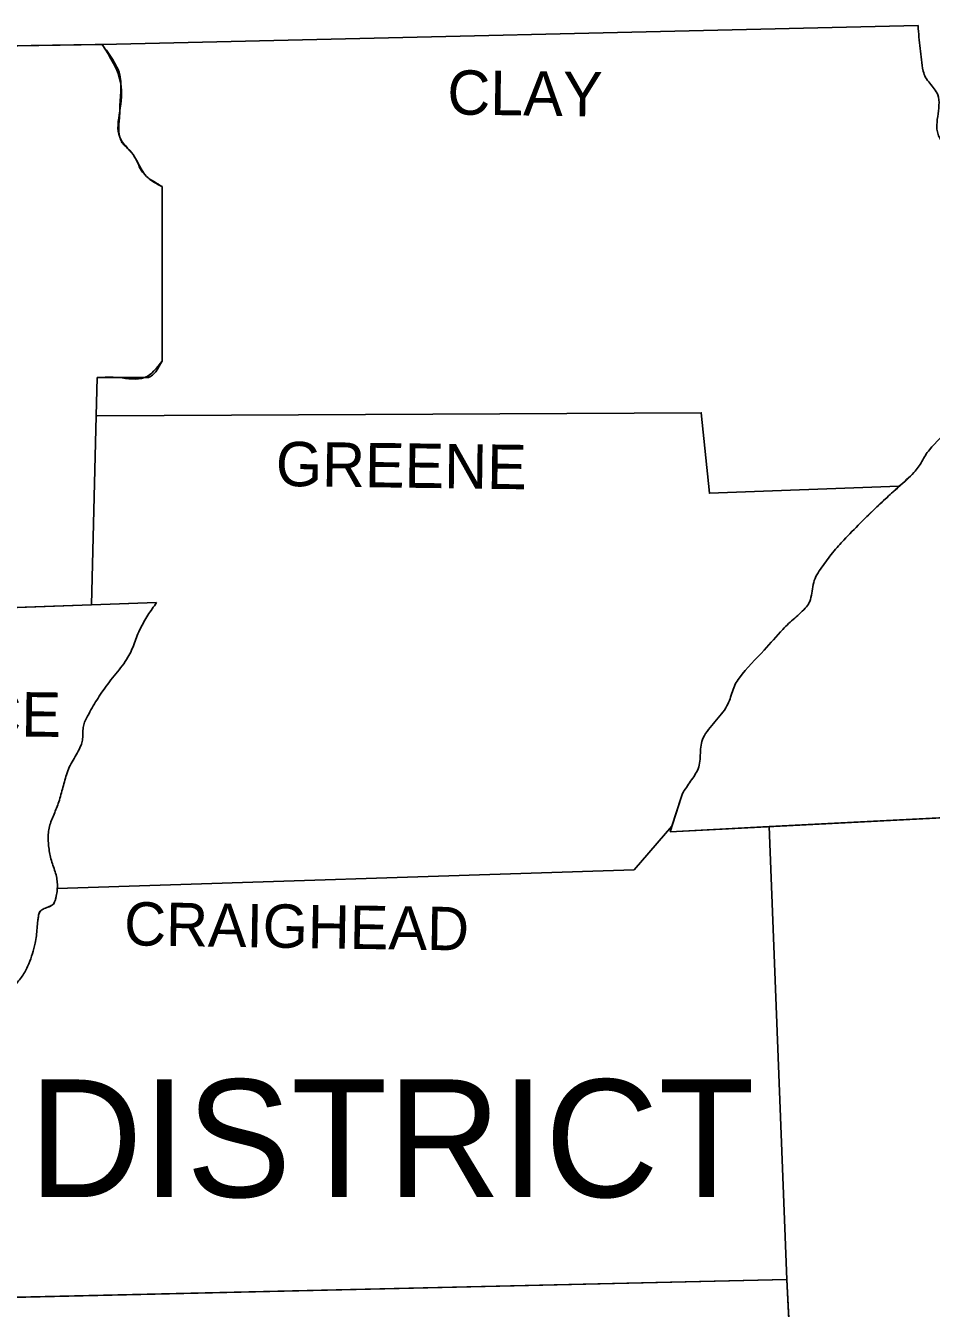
# Model space of a CAD drawing. Extents: x 1368042 to 1371376, y 380392 to 382637.
# Drawn here: x 1370078.3 to 1370261.4, y 381501.2 to 381760.7 of the extents above; entities that cross this region are included whole.
import ezdxf

# ---------------------------------------------------------------- set-up
doc = ezdxf.new("R2010")
doc.units = 0
doc.layers.add('Default', color=7, linetype='Continuous')
doc.layers.add('R_No Plot', color=7, linetype='Continuous')

msp = doc.modelspace()

# ---------------------------------------------------------------- linework, layer by layer
at = {"layer": 'Default'}
for p, q in [((1370092.56, 381681.8), (1370092.75, 381689.52)), ((1370208.64, 381597.64), (1370210.89, 381604.58))]:
    msp.add_line(p, q, dxfattribs=at)
for points in [[(1369113.15, 381751.13), (1369450.82, 381750.92), (1369747.14, 381751.54), (1370096.71, 381756.97), (1370258.76, 381760.73)], [(1370105.9, 381728.16), (1370105.9, 381692.87)], [(1370091.65, 381643.52), (1370092.56, 381681.8), (1370092.75, 381681.8), (1370214.91, 381682.42), (1370216.58, 381666.14), (1370254.9, 381667.53)], [(1370027.8, 381641.29), (1370104.79, 381643.99)], [(1370208.64, 381597.64), (1370367.14, 381605.79)], [(1370084.72, 381586.14), (1370201.33, 381589.92), (1370209, 381598.75)], [(1370228.64, 381598.67), (1370232.24, 381507.02), (1370236.49, 381421.47)], [(1370232.24, 381507.02), (1370038.09, 381502.59)]]:
    msp.add_lwpolyline(points, dxfattribs=at)
for points in [[(1370258.76, 381760.73), (1370258.94, 381758.43), (1370259.18, 381756.13), (1370259.47, 381753.83), (1370259.81, 381751.54), (1370260.29, 381750.25), (1370261.14, 381749.08), (1370262.05, 381747.94), (1370262.73, 381746.74), (1370262.99, 381744.62), (1370262.73, 381742.34), (1370262.57, 381740.06), (1370262.73, 381738.98), (1370263.15, 381737.97), (1370264.73, 381735.92), (1370266.7, 381734.21), (1370268.19, 381733.22), (1370269.73, 381732.34), (1370271.27, 381731.46), (1370272.75, 381730.45), (1370275.76, 381727.78), (1370277.05, 381726.22), (1370277.64, 381725.35), (1370278.18, 381724.4), (1370278.94, 381722.63), (1370279.38, 381720.85), (1370279.53, 381719.07), (1370279.43, 381717.3), (1370279.07, 381715.47), (1370278.56, 381713.66), (1370278.06, 381711.83), (1370277.76, 381709.99), (1370277.65, 381707.96), (1370277.58, 381705.92), (1370277.49, 381703.88), (1370277.35, 381701.84), (1370276.51, 381694.75), (1370276.12, 381691.48), (1370275.79, 381689.86), (1370275.56, 381689.06), (1370275.26, 381688.27), (1370273.08, 381685.38), (1370270.25, 381683.05), (1370269.05, 381682.1), (1370267.83, 381681.18), (1370266.62, 381680.26), (1370265.44, 381679.29), (1370261.06, 381674.91), (1370260.24, 381673.78), (1370259.53, 381672.57), (1370258.81, 381671.38), (1370257.93, 381670.31), (1370252.5, 381665.3), (1370247.07, 381660.08), (1370242.68, 381655.49), (1370241.48, 381654.1), (1370240.37, 381652.65), (1370239.31, 381651.16), (1370238.3, 381649.64), (1370237.66, 381648.07), (1370237.35, 381646.34), (1370236.99, 381644.64), (1370236.68, 381643.86), (1370236.21, 381643.17), (1370235.05, 381641.97), (1370233.82, 381640.86), (1370232.58, 381639.75), (1370231.41, 381638.57), (1370227.65, 381634.4), (1370222.63, 381628.76), (1370221.81, 381627.47), (1370221.24, 381626.02), (1370220.74, 381624.53), (1370220.13, 381623.12), (1370219.01, 381621.47), (1370217.7, 381619.91), (1370216.4, 381618.34), (1370215.33, 381616.65), (1370214.88, 381615.15), (1370214.75, 381613.53), (1370214.65, 381611.9), (1370214.28, 381610.38), (1370213.6, 381609.09), (1370212.77, 381607.85), (1370211.92, 381606.62), (1370211.15, 381605.37), (1370210.89, 381604.58)], [(1370093.76, 381756.93), (1370097.55, 381749.04), (1370097.34, 381743.4), (1370097.34, 381738.18), (1370100.05, 381734.63), (1370102.77, 381730.24), (1370105.9, 381728.16)], [(1370105.9, 381692.87), (1370102.35, 381689.52), (1370097.13, 381689.52), (1370092.75, 381689.52)], [(1370104.79, 381643.99), (1370103.03, 381641.45), (1370101.52, 381638.78), (1370100.87, 381637.33), (1370100.31, 381635.83), (1370099.73, 381634.35), (1370099.01, 381632.93), (1370097.84, 381631.21), (1370096.55, 381629.57), (1370095.24, 381627.94), (1370094, 381626.25), (1370091.98, 381623.09), (1370091.07, 381621.46), (1370090.24, 381619.78), (1370089.96, 381618.72), (1370089.89, 381617.59), (1370089.84, 381616.47), (1370089.61, 381615.39), (1370088.93, 381613.92), (1370088.12, 381612.49), (1370087.32, 381611.05), (1370086.69, 381609.55), (1370086.25, 381608.09), (1370085.85, 381606.62), (1370085.45, 381605.15), (1370085.02, 381603.7), (1370084.57, 381602.44), (1370084.06, 381601.2), (1370083.56, 381599.96), (1370083.14, 381598.69), (1370082.91, 381597.41), (1370082.87, 381596.09), (1370082.97, 381594.76), (1370083.14, 381593.47), (1370083.43, 381592.15), (1370083.84, 381590.85), (1370084.28, 381589.55), (1370084.6, 381588.25), (1370084.73, 381587.06), (1370084.7, 381585.85), (1370084.52, 381584.63), (1370084.37, 381584.03), (1370084.18, 381583.44), (1370083.56, 381582.73), (1370082.58, 381582.29), (1370081.62, 381581.86), (1370081.05, 381581.15), (1370080.89, 381580.41), (1370080.77, 381579.65), (1370080.63, 381578.12), (1370080.49, 381576.59), (1370080.22, 381575.09), (1370079.67, 381572.99), (1370078.96, 381570.92), (1370077.8, 381568.7), (1370077.08, 381567.69), (1370076.25, 381566.74), (1370075.3, 381565.89), (1370074.27, 381565.14), (1370073.24, 381564.41), (1370072.28, 381563.61), (1370071.21, 381562.45), (1370070.21, 381561.21), (1370069.21, 381559.98), (1370068.1, 381558.8), (1370066.64, 381557.65), (1370065.84, 381557.16), (1370064.97, 381556.72)]]:
    msp.add_spline(points, degree=3, dxfattribs=at)
at = {"layer": 'R_No Plot'}
for p, q in [((1370093.76, 381756.93), (1369939.22, 381754.53)), ((1370105.9, 381692.87), (1370105.9, 381728.16)), ((1370105.9, 381728.16), (1370105.9, 381692.87)), ((1370092.56, 381681.8), (1370092.75, 381689.52)), ((1370092.75, 381689.52), (1370092.56, 381681.8)), ((1370091.65, 381643.52), (1370092.56, 381681.8)), ((1370027.8, 381641.29), (1370091.65, 381643.52)), ((1370091.65, 381643.52), (1370027.8, 381641.29)), ((1370104.79, 381643.99), (1370091.65, 381643.52)), ((1370091.65, 381643.52), (1370104.79, 381643.99)), ((1370209, 381598.75), (1370210.89, 381604.58)), ((1370208.64, 381597.64), (1370209, 381598.75)), ((1370228.64, 381598.67), (1370208.64, 381597.64)), ((1370232.24, 381507.02), (1370228.64, 381598.67)), ((1370038.09, 381502.59), (1370232.24, 381507.02)), ((1370232.24, 381507.02), (1370038.09, 381502.59)), ((1370236.49, 381421.47), (1370232.24, 381507.02))]:
    msp.add_line(p, q, dxfattribs=at)
for points in [[(1370258.76, 381760.73), (1370096.71, 381756.97), (1370093.76, 381756.93)], [(1370254.9, 381667.53), (1370216.58, 381666.14), (1370214.91, 381682.42), (1370092.75, 381681.8), (1370092.56, 381681.8), (1370091.65, 381643.52)], [(1370092.56, 381681.8), (1370092.75, 381681.8), (1370214.91, 381682.42), (1370216.58, 381666.14), (1370254.9, 381667.53)], [(1370254.9, 381667.53), (1370254.9, 381667.53)], [(1370254.9, 381667.53), (1370254.9, 381667.53)], [(1370367.14, 381605.79), (1370365.81, 381605.72), (1370228.64, 381598.67)], [(1370084.72, 381586.14), (1370201.33, 381589.92), (1370209, 381598.75)], [(1370209, 381598.75), (1370201.33, 381589.92), (1370084.72, 381586.14)], [(1370228.64, 381598.67), (1370232.24, 381507.02), (1370236.49, 381421.47)]]:
    msp.add_lwpolyline(points, dxfattribs=at)
for points in [[(1370277.59, 381706.18), (1370277.65, 381707.96), (1370277.76, 381709.99), (1370278.06, 381711.83), (1370278.56, 381713.66), (1370279.07, 381715.47), (1370279.43, 381717.3), (1370279.53, 381719.07), (1370279.38, 381720.85), (1370278.94, 381722.63), (1370278.18, 381724.4), (1370277.64, 381725.35), (1370277.05, 381726.22), (1370275.76, 381727.78), (1370272.75, 381730.45), (1370271.27, 381731.46), (1370269.73, 381732.34), (1370268.19, 381733.22), (1370266.7, 381734.21), (1370264.73, 381735.92), (1370263.15, 381737.97), (1370262.73, 381738.98), (1370262.57, 381740.06), (1370262.73, 381742.34), (1370262.99, 381744.62), (1370262.73, 381746.74), (1370262.05, 381747.94), (1370261.14, 381749.08), (1370260.29, 381750.25), (1370259.81, 381751.54), (1370259.47, 381753.83), (1370259.18, 381756.13), (1370258.94, 381758.43), (1370258.76, 381760.73)], [(1370105.9, 381728.16), (1370102.77, 381730.24), (1370100.05, 381734.63), (1370097.34, 381738.18), (1370097.34, 381743.4), (1370097.55, 381749.04), (1370093.76, 381756.93)], [(1370093.76, 381756.93), (1370094.35, 381756.14), (1370094.93, 381755.35), (1370095.48, 381754.54), (1370095.99, 381753.72)], [(1370097.34, 381738.18), (1370097.72, 381737.24), (1370098.37, 381736.44), (1370099.13, 381735.69), (1370099.5, 381735.31), (1370099.84, 381734.92)], [(1370104.69, 381728.92), (1370105.3, 381728.55), (1370105.9, 381728.16)], [(1370254.9, 381667.53), (1370257.93, 381670.31), (1370258.81, 381671.38), (1370259.53, 381672.57), (1370260.24, 381673.78), (1370261.06, 381674.91), (1370265.44, 381679.29), (1370266.62, 381680.26), (1370267.83, 381681.18), (1370269.05, 381682.1), (1370270.25, 381683.05), (1370273.08, 381685.38), (1370275.26, 381688.27), (1370275.56, 381689.06), (1370275.79, 381689.86), (1370276.12, 381691.48), (1370276.51, 381694.75), (1370277.35, 381701.84), (1370277.49, 381703.88), (1370277.58, 381705.92), (1370277.59, 381706.18)], [(1370092.75, 381689.52), (1370097.13, 381689.52), (1370102.35, 381689.52), (1370105.9, 381692.87)], [(1370243.75, 381656.64), (1370247.07, 381660.08), (1370249.77, 381662.7), (1370252.5, 381665.3), (1370254.9, 381667.53)], [(1370210.89, 381604.58), (1370211.15, 381605.37), (1370211.92, 381606.62), (1370212.77, 381607.85), (1370213.6, 381609.09), (1370214.28, 381610.38), (1370214.65, 381611.9), (1370214.75, 381613.53), (1370214.88, 381615.15), (1370215.33, 381616.65), (1370216.4, 381618.34), (1370217.7, 381619.91), (1370219.01, 381621.47), (1370220.13, 381623.12), (1370220.74, 381624.53), (1370221.24, 381626.02), (1370221.81, 381627.47), (1370222.63, 381628.76), (1370227.65, 381634.4), (1370231.41, 381638.57), (1370232.58, 381639.75), (1370233.82, 381640.86), (1370235.05, 381641.97), (1370236.21, 381643.17), (1370236.68, 381643.86), (1370236.99, 381644.64), (1370237.35, 381646.34), (1370237.66, 381648.07), (1370238.3, 381649.64), (1370239.31, 381651.16), (1370240.37, 381652.65), (1370241.48, 381654.1), (1370242.68, 381655.49), (1370243.75, 381656.64)], [(1370089.28, 381614.6), (1370089.61, 381615.39), (1370089.84, 381616.47), (1370089.89, 381617.59), (1370089.96, 381618.72), (1370090.24, 381619.78), (1370091.07, 381621.46), (1370091.98, 381623.09), (1370094, 381626.25), (1370095.24, 381627.94), (1370096.55, 381629.57), (1370097.84, 381631.21), (1370099.01, 381632.93), (1370099.73, 381634.35), (1370100.31, 381635.83), (1370100.87, 381637.33), (1370101.52, 381638.78), (1370103.03, 381641.45), (1370104.79, 381643.99)], [(1370104.79, 381643.99), (1370103.03, 381641.45), (1370101.52, 381638.78), (1370100.87, 381637.33), (1370100.31, 381635.83), (1370099.73, 381634.35), (1370099.01, 381632.93), (1370097.84, 381631.21), (1370096.55, 381629.57), (1370095.24, 381627.94), (1370094, 381626.25), (1370091.98, 381623.09), (1370091.07, 381621.46), (1370090.24, 381619.78), (1370089.96, 381618.72), (1370089.89, 381617.59), (1370089.84, 381616.47), (1370089.61, 381615.39), (1370089.28, 381614.6)], [(1370083.51, 381582.71), (1370083.56, 381582.73), (1370084.18, 381583.44), (1370084.37, 381584.03), (1370084.52, 381584.63), (1370084.7, 381585.85), (1370084.73, 381587.06), (1370084.6, 381588.25), (1370084.28, 381589.55), (1370083.84, 381590.85), (1370083.43, 381592.15), (1370083.14, 381593.47), (1370082.97, 381594.76), (1370082.87, 381596.09), (1370082.91, 381597.41), (1370083.14, 381598.69), (1370083.56, 381599.96), (1370084.06, 381601.2), (1370084.57, 381602.44), (1370085.02, 381603.7), (1370085.45, 381605.15), (1370085.85, 381606.62), (1370086.25, 381608.09), (1370086.69, 381609.55), (1370087.32, 381611.05), (1370088.12, 381612.49), (1370088.93, 381613.92), (1370089.28, 381614.6)], [(1370089.28, 381614.6), (1370088.93, 381613.92), (1370088.12, 381612.49), (1370087.32, 381611.05), (1370086.69, 381609.55), (1370086.25, 381608.09), (1370085.85, 381606.62), (1370085.45, 381605.15), (1370085.02, 381603.7), (1370084.57, 381602.44), (1370084.06, 381601.2), (1370083.56, 381599.96), (1370083.14, 381598.69), (1370082.91, 381597.41), (1370082.87, 381596.09), (1370082.97, 381594.76), (1370083.14, 381593.47), (1370083.43, 381592.15), (1370083.84, 381590.85), (1370084.28, 381589.55), (1370084.6, 381588.25), (1370084.73, 381587.06), (1370084.72, 381586.14)], [(1370084.72, 381586.14), (1370084.7, 381585.85), (1370084.52, 381584.63), (1370084.37, 381584.03), (1370084.18, 381583.44), (1370083.56, 381582.73), (1370083.51, 381582.71)], [(1370064.97, 381556.72), (1370065.84, 381557.16), (1370066.64, 381557.65), (1370068.1, 381558.8), (1370069.21, 381559.98), (1370070.21, 381561.21), (1370071.21, 381562.45), (1370072.28, 381563.61), (1370073.24, 381564.41), (1370074.27, 381565.14), (1370075.3, 381565.89), (1370076.25, 381566.74), (1370077.08, 381567.69), (1370077.8, 381568.7), (1370078.96, 381570.92), (1370079.67, 381572.99), (1370080.22, 381575.09), (1370080.49, 381576.59), (1370080.63, 381578.12), (1370080.77, 381579.65), (1370080.89, 381580.41), (1370081.05, 381581.15), (1370081.62, 381581.86), (1370082.58, 381582.29), (1370083.51, 381582.71)], [(1370083.51, 381582.71), (1370082.58, 381582.29), (1370081.62, 381581.86), (1370081.05, 381581.15), (1370080.89, 381580.41), (1370080.77, 381579.65), (1370080.63, 381578.12), (1370080.49, 381576.59), (1370080.22, 381575.09), (1370079.67, 381572.99), (1370078.96, 381570.92), (1370077.8, 381568.7), (1370077.08, 381567.69), (1370076.25, 381566.74), (1370075.3, 381565.89), (1370074.27, 381565.14), (1370073.24, 381564.41), (1370072.28, 381563.61), (1370071.21, 381562.45), (1370070.21, 381561.21), (1370069.21, 381559.98), (1370068.1, 381558.8), (1370066.64, 381557.65), (1370065.84, 381557.16), (1370064.97, 381556.72)]]:
    msp.add_spline(points, degree=3, dxfattribs=at)
for points in [[(1370095.99, 381753.72), (1370096.87, 381752.25), (1370097.51, 381750.7), (1370097.55, 381749.04), (1370097.6, 381747.16), (1370097.38, 381745.28), (1370097.34, 381743.4), (1370097.3, 381741.66), (1370097.01, 381739.92), (1370097.34, 381738.18)], [(1370099.84, 381734.92), (1370099.92, 381734.82), (1370099.99, 381734.73), (1370100.05, 381734.63), (1370100.99, 381733.24), (1370101.47, 381731.47), (1370102.72, 381730.29)], [(1370102.72, 381730.29), (1370102.73, 381730.28), (1370102.75, 381730.26), (1370102.77, 381730.24), (1370103.35, 381729.71), (1370104.02, 381729.31), (1370104.69, 381728.92)], [(1370105.9, 381692.87), (1370105.09, 381691.4), (1370103.98, 381689.52), (1370102.35, 381689.52), (1370100.61, 381689.52), (1370098.87, 381689.52), (1370097.13, 381689.52), (1370095.67, 381689.52), (1370094.21, 381689.52), (1370092.75, 381689.52)]]:
    msp.add_open_spline(points, degree=3, dxfattribs=at)

# ---------------------------------------------------------------- texts
at = {"layer": 'Default'}
for s, height, rotation, p in [('CLAY', 8.978, 359.2258, (1370163.54, 381742.77)), ('GREENE', 8.981, 359.2361, (1370128.87, 381667.6)), ('LAWRENCE', 8.981, 359.2678, (1370017.36, 381617.69)), ('CRAIGHEAD', 8.772, 359.1159, (1370098.18, 381574.67))]:
    msp.add_text(s, height=height, rotation=rotation, dxfattribs=at).set_placement(p)
msp.add_text('DISTRICT', height=23.805, dxfattribs=at).set_placement((1370078.96, 381523.72))

doc.saveas('drawing.dxf')
